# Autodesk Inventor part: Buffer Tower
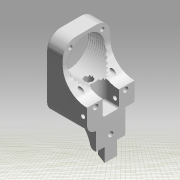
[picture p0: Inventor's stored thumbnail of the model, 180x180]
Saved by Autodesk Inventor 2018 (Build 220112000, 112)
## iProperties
Created: 2013-05
Part Number: Buffer Tower
Material: Generic
Document SubType Name: Modeling
Designer: johne
Appearance: Generic
Title: C:\Documents and Settings\Administrator\My Documents\AR-15 - Lower Receiver V5.1gs_buf_tower.STEP.stp
Sending System: ACIS
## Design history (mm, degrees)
feature "Base1"
sketch "Sketch1"
  geometry: L1 (4.505, 0)-(0, 0) reference; L2 (1.211, 0)-(-4.99, 0); L3 (-4.99, 0)-(-4.99, -3.22); L4 (-4.99, -3.22)-(1.211, -3.22); L5 (1.211, -3.22)-(1.211, 0); 1 further point
  constraints: 8 end point, 2 parallel, 1 horizontal, 1 perpendicular, 1 point on line
extrude "Extrusion1" cut sketch "Sketch1" distance "d0" = 25.4; taper "d1" = 0 deg
body "Solid1"
